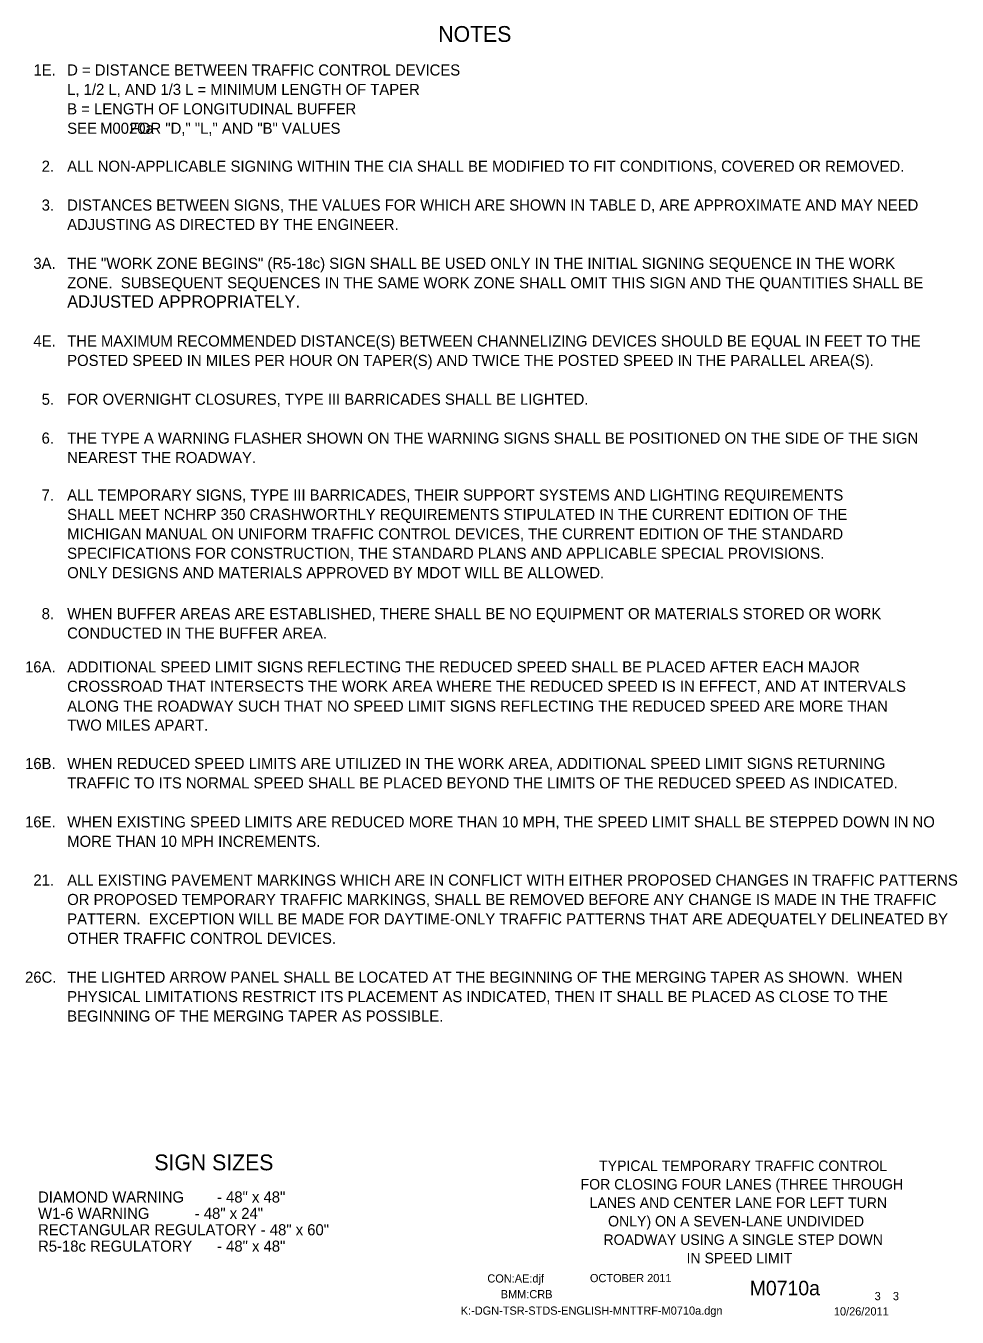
# Model space of a CAD drawing. Extents: x 16731 to 19504, y 5932 to 7446.
# Drawn here: x 18799 to 19504, y 5932 to 6909 of the extents above; entities that cross this region are included whole.
import ezdxf

# ---------------------------------------------------------------- set-up
doc = ezdxf.new("R2010")
doc.units = 0
for name, color, linetype in [('BORDER', 7, 'Continuous'), ('BORDER_SIGNAL_WO', 7, 'Continuous'), ('TYPICAL_TEXT_DIMEN_PR', 7, 'Continuous')]:
    doc.layers.add(name, color=color, linetype=linetype)

msp = doc.modelspace()

# ---------------------------------------------------------------- linework, layer by layer
at = {"layer": 'BORDER'}
msp.add_line((19347.25, 6011.25), (19347.25, 6011.25), dxfattribs=at)

# ---------------------------------------------------------------- texts
at = {"layer": 'BORDER_SIGNAL_WO'}
for s, height, p in [('TYPICAL TEMPORARY TRAFFIC CONTROL', 7.9737, (19233.21, 6042.43)), ('FOR CLOSING FOUR LANES (THREE THROUGH', 7.9737, (19219.21, 6028.45)), ('LANES AND CENTER LANE FOR LEFT TURN', 7.9737, (19226.04, 6014.48)), ('ONLY) ON A SEVEN-LANE UNDIVIDED', 7.9737, (19240.02, 6000.5)), ('ROADWAY USING A SINGLE STEP DOWN', 7.9737, (19236.54, 5986.53)), ('IN SPEED LIMIT', 7.9737, (19299.42, 5972.55)), ('CON:AE:djf', 6.2, (19148.69, 5958.06)), ('    OCTOBER 2011    ', 6.2, (19217.08, 5958.34)), ('BMM:CRB   ', 6.2, (19158.81, 5946.17)), ('    M0710a   ', 11, (19330.86, 5948.38)), (' 3    3 ', 6.2, (19439.45, 5944.7)), ('K:-DGN-TSR-STDS-ENGLISH-MNTTRF-M0710a.dgn        ', 6.2, (19128.55, 5933.71)), ('10/26/2011    ', 6.2, (19410.93, 5933.13))]:
    msp.add_text(s, height=height, dxfattribs=at).set_placement(p)
at = {"layer": 'TYPICAL_TEXT_DIMEN_PR'}
for s, height, p in [('NOTES', 12, (19111.55, 6897)), ('1E.', 8.4, (18805.19, 6871.56)), ('D = DISTANCE BETWEEN TRAFFIC CONTROL DEVICES', 8.4, (18830.7, 6871.56)), ('L, 1/2 L, AND 1/3 L = MINIMUM LENGTH OF TAPER', 8.4, (18830.7, 6856.86)), ('B = LENGTH OF LONGITUDINAL BUFFER', 8.4, (18830.7, 6842.16)), ('SEE        FOR "D," "L," AND "B" VALUES', 8.4, (18830.7, 6827.46)), ('M0020a', 8.4, (18855.62, 6827.46)), ('2.', 8.4, (18811.39, 6798.75)), ('ALL NON-APPLICABLE SIGNING WITHIN THE CIA SHALL BE MODIFIED TO FIT CONDITIONS, COVERED OR REMOVED.', 8.4, (18830.7, 6798.75)), ('3.', 8.4, (18811.39, 6769.35)), ('DISTANCES BETWEEN SIGNS, THE VALUES FOR WHICH ARE SHOWN IN TABLE D, ARE APPROXIMATE AND MAY NEED', 8.4, (18830.7, 6769.35)), ('ADJUSTING AS DIRECTED BY THE ENGINEER.', 8.4, (18830.7, 6754.65)), ('THE "WORK ZONE BEGINS" (R5-18c) SIGN SHALL BE USED ONLY IN THE INITIAL SIGNING SEQUENCE IN THE WORK', 8.4, (18830.7, 6725.25)), ('3A.', 8.4, (18805.09, 6725.25)), ('ZONE.  SUBSEQUENT SEQUENCES IN THE SAME WORK ZONE SHALL OMIT THIS SIGN AND THE QUANTITIES SHALL BE', 8.4, (18830.7, 6710.55)), ('ADJUSTED APPROPRIATELY.', 9.3, (18830.7, 6695.85)), ('THE MAXIMUM RECOMMENDED DISTANCE(S) BETWEEN CHANNELIZING DEVICES SHOULD BE EQUAL IN FEET TO THE', 8.4, (18830.7, 6666.45)), ('4E.', 8.4, (18805.13, 6666.45)), ('POSTED SPEED IN MILES PER HOUR ON TAPER(S) AND TWICE THE POSTED SPEED IN THE PARALLEL AREA(S).', 8.4, (18830.7, 6651.75)), ('5.', 8.4, (18811.39, 6622.35)), ('FOR OVERNIGHT CLOSURES, TYPE III BARRICADES SHALL BE LIGHTED.', 8.4, (18830.7, 6622.35)), ('6.', 8.4, (18811.34, 6592.95)), ('THE TYPE A WARNING FLASHER SHOWN ON THE WARNING SIGNS SHALL BE POSITIONED ON THE SIDE OF THE SIGN', 8.4, (18830.7, 6592.95)), ('NEAREST THE ROADWAY.', 8.4, (18830.7, 6578.25)), ('7.', 8.4, (18811.34, 6549.87)), ('ALL TEMPORARY SIGNS, TYPE III BARRICADES, THEIR SUPPORT SYSTEMS AND LIGHTING REQUIREMENTS', 8.4, (18830.7, 6549.89)), ('SHALL MEET NCHRP 350 CRASHWORTHLY REQUIREMENTS STIPULATED IN THE CURRENT EDITION OF THE', 8.4, (18830.7, 6535.19)), ('MICHIGAN MANUAL ON UNIFORM TRAFFIC CONTROL DEVICES, THE CURRENT EDITION OF THE STANDARD', 8.4, (18830.7, 6520.49)), ('SPECIFICATIONS FOR CONSTRUCTION, THE STANDARD PLANS AND APPLICABLE SPECIAL PROVISIONS.', 8.4, (18830.7, 6505.79)), ('ONLY DESIGNS AND MATERIALS APPROVED BY MDOT WILL BE ALLOWED.', 8.4, (18830.7, 6491.09)), ('8.', 8.4, (18811.39, 6460.11)), ('WHEN BUFFER AREAS ARE ESTABLISHED, THERE SHALL BE NO EQUIPMENT OR MATERIALS STORED OR WORK     ', 8.4, (18830.7, 6460.11)), ('CONDUCTED IN THE BUFFER AREA.', 8.4, (18830.7, 6445.41)), ('16A.', 8.4, (18798.84, 6419.83)), ('ADDITIONAL SPEED LIMIT SIGNS REFLECTING THE REDUCED SPEED SHALL BE PLACED AFTER EACH MAJOR', 8.4, (18830.7, 6419.83)), ('CROSSROAD THAT INTERSECTS THE WORK AREA WHERE THE REDUCED SPEED IS IN EFFECT, AND AT INTERVALS', 8.4, (18830.7, 6405.13)), ('ALONG THE ROADWAY SUCH THAT NO SPEED LIMIT SIGNS REFLECTING THE REDUCED SPEED ARE MORE THAN', 8.4, (18830.7, 6390.13)), ('TWO MILES APART.', 8.4, (18830.7, 6375.73)), ('16B.', 8.4, (18798.84, 6346.67)), ('WHEN REDUCED SPEED LIMITS ARE UTILIZED IN THE WORK AREA, ADDITIONAL SPEED LIMIT SIGNS RETURNING', 8.4, (18830.7, 6346.73)), ('TRAFFIC TO ITS NORMAL SPEED SHALL BE PLACED BEYOND THE LIMITS OF THE REDUCED SPEED AS INDICATED.', 8.4, (18830.7, 6332.03)), ('16E.', 8.4, (18798.83, 6302.5)), ('WHEN EXISTING SPEED LIMITS ARE REDUCED MORE THAN 10 MPH, THE SPEED LIMIT SHALL BE STEPPED DOWN IN NO', 8.4, (18830.7, 6302.5)), ('MORE THAN 10 MPH INCREMENTS.', 8.4, (18830.7, 6287.8)), ('21.', 8.4, (18805.14, 6258.47)), ('ALL EXISTING PAVEMENT MARKINGS WHICH ARE IN CONFLICT WITH EITHER PROPOSED CHANGES IN TRAFFIC PATTERNS', 8.4, (18830.7, 6258.47)), ('OR PROPOSED TEMPORARY TRAFFIC MARKINGS, SHALL BE REMOVED BEFORE ANY CHANGE IS MADE IN THE TRAFFIC', 8.4, (18830.7, 6243.77)), ('PATTERN.  EXCEPTION WILL BE MADE FOR DAYTIME-ONLY TRAFFIC PATTERNS THAT ARE ADEQUATELY DELINEATED BY', 8.4, (18830.7, 6229.07)), ('OTHER TRAFFIC CONTROL DEVICES.', 8.4, (18830.7, 6214.37)), ('26C.', 8.4, (18798.83, 6184.97)), ('THE LIGHTED ARROW PANEL SHALL BE LOCATED AT THE BEGINNING OF THE MERGING TAPER AS SHOWN.  WHEN', 8.4, (18830.7, 6184.97)), ('PHYSICAL LIMITATIONS RESTRICT ITS PLACEMENT AS INDICATED, THEN IT SHALL BE PLACED AS CLOSE TO THE', 8.4, (18830.7, 6170.27)), ('BEGINNING OF THE MERGING TAPER AS POSSIBLE.', 8.4, (18830.7, 6155.57)), ('SIGN SIZES', 12, (18896.69, 6043)), ('DIAMOND WARNING        - 48" x 48"', 8.4, (18808.65, 6018.6)), ('W1-6 WARNING           - 48" x 24"', 8.4, (18808.65, 6006.2)), ('RECTANGULAR REGULATORY - 48" x 60"', 8.4, (18808.65, 5993.8)), ('R5-18c REGULATORY      - 48" x 48"', 8.4, (18808.65, 5981.4))]:
    msp.add_text(s, height=height, dxfattribs=at).set_placement(p)

doc.saveas('drawing.dxf')
